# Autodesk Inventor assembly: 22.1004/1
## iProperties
Created: 2011-07
Part Number: 22.1004/1
Document SubType Name: Assembly
Designer: Administrator
Description: END CAP 45X45 GRAY
Vendor: S
Mass: 6.19693 g
Surface Area: 64.7898 cm^2
Volume: 5.84616 cm^3
Density: 1.06 g/cm^3
Author: Administrator
